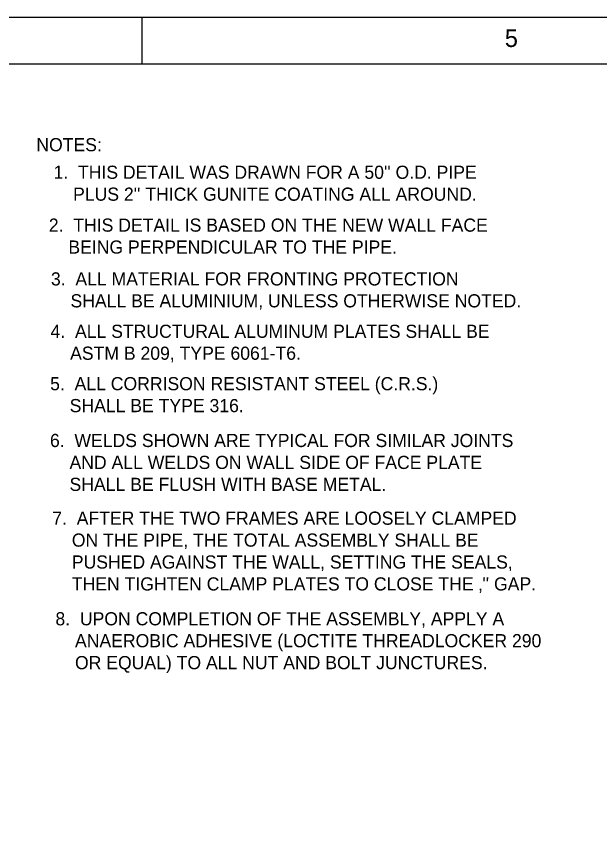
# Model space of a CAD drawing. Extents: x 22388.1 to 22405.7, y 22369.6 to 22390.4.
# Drawn here: x 22398.639 to 22400.714, y 22377.974 to 22380.949 of the extents above; entities that cross this region are included whole.
import ezdxf

# ---------------------------------------------------------------- set-up
doc = ezdxf.new("R2010")
doc.units = 0
for name, color, linetype in [('Level 1', 7, 'Continuous'), ('Level 10', 7, 'Continuous'), ('S-ANNO-TEXT', 7, 'Continuous')]:
    doc.layers.add(name, color=color, linetype=linetype)

msp = doc.modelspace()

# ---------------------------------------------------------------- linework, layer by layer
at = {"layer": 'Level 1'}
msp.add_lwpolyline([(22388.1232, 22380.9477), (22402.7899, 22380.9477), (22402.7899, 22369.6143), (22388.1232, 22369.6143)], close=True, dxfattribs=at)
at = {"layer": 'Level 10'}
msp.add_line((22399.0859, 22380.781), (22399.0859, 22380.949), dxfattribs=at)
at = {"layer": 'S-ANNO-TEXT'}
msp.add_line((22388.6232, 22380.781), (22401.7059, 22380.781), dxfattribs=at)

# ---------------------------------------------------------------- texts
at = {"layer": 'Level 1'}
msp.add_text('5', height=0.0624, dxfattribs=at).set_placement((22400.3779, 22380.841))
at = {"layer": 'S-ANNO-TEXT'}
for s, height, p in [('NOTES:', 0.04688, (22398.7086, 22380.4693)), ("1.  THIS DETAIL WAS DRAWN FOR A 50'' O.D. PIPE", 0.046875, (22398.7699, 22380.3711)), ("    PLUS 2'' THICK GUNITE COATING ALL AROUND.", 0.046875, (22398.7699, 22380.293)), ('2.  THIS DETAIL IS BASED ON THE NEW WALL FACE', 0.046875, (22398.7532, 22380.1827)), ('    BEING PERPENDICULAR TO THE PIPE.', 0.046875, (22398.7532, 22380.1045)), ('3.  ALL MATERIAL FOR FRONTING PROTECTION', 0.046875, (22398.7607, 22379.991)), ('    SHALL BE ALUMINIUM, UNLESS OTHERWISE NOTED.', 0.046875, (22398.7607, 22379.9129)), ('4.  ALL STRUCTURAL ALUMINUM PLATES SHALL BE', 0.046875, (22398.7593, 22379.8043)), ('    ASTM B 209, TYPE 6061-T6.', 0.046875, (22398.7593, 22379.7261)), ('5.  ALL CORRISON RESISTANT STEEL (C.R.S.)', 0.046875, (22398.7578, 22379.6175)), ('    SHALL BE TYPE 316.', 0.046875, (22398.7578, 22379.5394)), ('6.  WELDS SHOWN ARE TYPICAL FOR SIMILAR JOINTS', 0.046875, (22398.7572, 22379.4151)), ('    AND ALL WELDS ON WALL SIDE OF FACE PLATE', 0.046875, (22398.7572, 22379.3369)), ('    SHALL BE FLUSH WITH BASE METAL.', 0.046875, (22398.7572, 22379.2588)), ('7.  AFTER THE TWO FRAMES ARE LOOSELY CLAMPED', 0.046875, (22398.7654, 22379.1382)), ('    ON THE PIPE, THE TOTAL ASSEMBLY SHALL BE', 0.046875, (22398.7654, 22379.06)), ('    PUSHED AGAINST THE WALL, SETTING THE SEALS,', 0.046875, (22398.7654, 22378.9819)), ("    THEN TIGHTEN CLAMP PLATES TO CLOSE THE ‚'' GAP.", 0.046875, (22398.7654, 22378.9038)), ('8.  UPON COMPLETION OF THE ASSEMBLY, APPLY A', 0.046875, (22398.7767, 22378.7796)), ('    ANAEROBIC ADHESIVE (LOCTITE THREADLOCKER 290', 0.046875, (22398.7767, 22378.7014)), ('    OR EQUAL) TO ALL NUT AND BOLT JUNCTURES.', 0.046875, (22398.7767, 22378.6233))]:
    msp.add_text(s, height=height, dxfattribs=at).set_placement(p)

doc.saveas('drawing.dxf')
